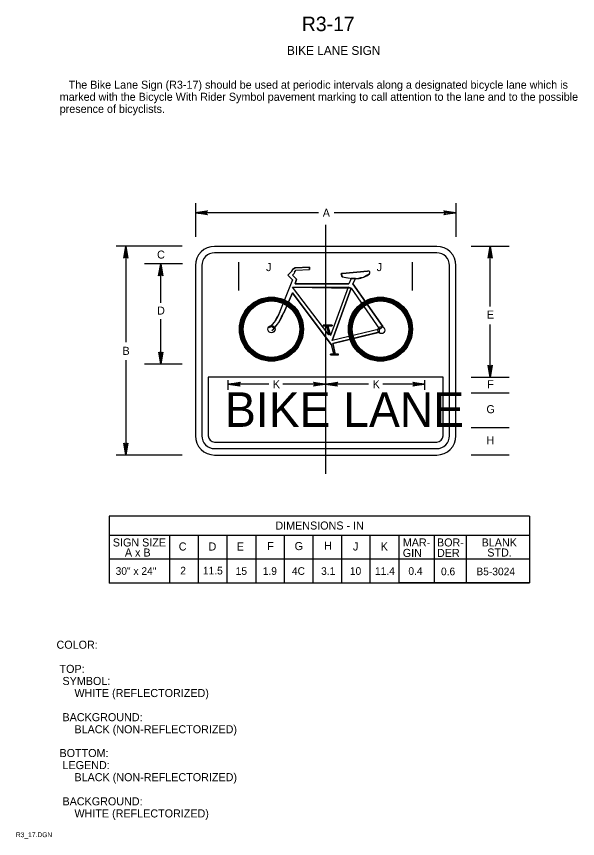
# Model space of a CAD drawing. Extents: x 0.013 to 0.187, y 0.004 to 0.259.
import ezdxf

# ---------------------------------------------------------------- set-up
doc = ezdxf.new("R2010")
doc.units = 0
for name, color, linetype in [('1', 7, 'Continuous'), ('2', 7, 'Continuous'), ('3', 7, 'Continuous')]:
    doc.layers.add(name, color=color, linetype=linetype)

# ---------------------------------------------------------------- blocks, each defined once
blk = doc.blocks.new('RARROW')
at = {"layer": '3'}
for p, q in [((-2.156, 0.28500000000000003), (-2.2665, 0.384625)), ((-2.2665, 0.384625), (0, 0)), ((0, 0), (-2.2665, -0.379125)), ((-2.156, 0.28500000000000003), (-2.075625, 0.12075)), ((0, 0), (-2.156, 0.28500000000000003)), ((-2.14975, -0.2705), (0, 0)), ((-2.075625, 0.12075), (0, 0)), ((0, 0), (-2.074, -0.108)), ((-2.2665, -0.379125), (-2.14975, -0.2705)), ((-2.074, -0.108), (-2.14975, -0.2705))]:
    blk.add_line(p, q, dxfattribs=at)

msp = doc.modelspace()

# ---------------------------------------------------------------- linework, layer by layer
at = {"layer": '1'}
msp.add_line((0.10875, 0.1945), (0.10875, 0.11721715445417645), dxfattribs=at)
at = {"layer": '3'}
for p, q in [((0.068275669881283, 0.20125), (0.068275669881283, 0.19081538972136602)), ((0.149275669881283, 0.20125), (0.149275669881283, 0.19081538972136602)), ((0.1065, 0.19825), (0.06825, 0.19825)), ((0.149275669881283, 0.19825), (0.1114455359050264, 0.19825)), ((0.06421562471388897, 0.18788002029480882), (0.04370848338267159, 0.18788002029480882)), ((0.046625, 0.18787500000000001), (0.046625, 0.158059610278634)), ((0.14327566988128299, 0.18781538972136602), (0.074275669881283, 0.18781538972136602)), ((0.16577656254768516, 0.18781538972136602), (0.15402656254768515, 0.18781538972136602)), ((0.15990156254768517, 0.169125), (0.15990156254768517, 0.18781538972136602)), ((0.14327566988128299, 0.18581538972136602), (0.074275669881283, 0.18581538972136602)), ((0.06424285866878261, 0.18236952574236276), (0.052492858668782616, 0.18236952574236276)), ((0.0575, 0.17025), (0.0575, 0.182375)), ((0.068275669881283, 0.18181538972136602), (0.068275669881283, 0.12901539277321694)), ((0.07027566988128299, 0.18181538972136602), (0.07027566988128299, 0.12901539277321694)), ((0.08175, 0.174125), (0.08175, 0.182875)), ((0.09925, 0.181125), (0.10375000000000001, 0.181375)), ((0.10375000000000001, 0.181375), (0.10375000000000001, 0.180625)), ((0.13575, 0.174125), (0.13575, 0.182875)), ((0.147275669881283, 0.12901539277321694), (0.147275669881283, 0.18181538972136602)), ((0.149275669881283, 0.12901539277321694), (0.149275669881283, 0.18181538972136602)), ((0.097, 0.178875), (0.09825, 0.180125)), ((0.0985, 0.177375), (0.097, 0.178875)), ((0.09825, 0.180125), (0.0985, 0.180625)), ((0.0985, 0.180625), (0.09875, 0.180875)), ((0.0985, 0.178875), (0.099, 0.179375)), ((0.09975, 0.177625), (0.0985, 0.178875)), ((0.09875, 0.180875), (0.09925, 0.181125)), ((0.099, 0.179375), (0.0995, 0.180375)), ((0.099, 0.179875), (0.0995, 0.180375)), ((0.0995, 0.180375), (0.10375000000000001, 0.180625)), ((0.114, 0.179375), (0.12175, 0.180125)), ((0.0985, 0.177375), (0.0945, 0.167625)), ((0.09975, 0.177625), (0.09925, 0.176125)), ((0.09925, 0.176125), (0.116, 0.176125)), ((0.11675, 0.177875), (0.116, 0.176125)), ((0.11800000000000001, 0.177875), (0.11725000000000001, 0.176125)), ((0.11725000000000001, 0.176125), (0.1265, 0.162875)), ((0.0985, 0.175125), (0.11575, 0.175125)), ((0.10975, 0.160375), (0.0985, 0.175125)), ((0.11575, 0.175125), (0.11025, 0.160125)), ((0.11675, 0.174875), (0.11075, 0.15862500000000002)), ((0.11675, 0.174875), (0.1255, 0.162125)), ((0.0985, 0.173375), (0.09575, 0.167125)), ((0.1105, 0.15737500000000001), (0.0985, 0.173375)), ((0.0575, 0.15125), (0.0575, 0.16522262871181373)), ((0.108, 0.163375), (0.109, 0.163375)), ((0.108, 0.163375), (0.108, 0.163125)), ((0.109, 0.163375), (0.11075, 0.163375)), ((0.11075, 0.163375), (0.11075, 0.163125)), ((0.15987500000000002, 0.147125), (0.15987500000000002, 0.16359756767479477)), ((0.108, 0.163125), (0.109, 0.163125)), ((0.109, 0.163125), (0.10975, 0.160375)), ((0.1095, 0.163125), (0.11075, 0.163125)), ((0.1095, 0.163125), (0.11025, 0.160125)), ((0.1255, 0.162125), (0.11075, 0.15862500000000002)), ((0.12525, 0.161125), (0.111, 0.15762500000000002)), ((0.1105, 0.15737500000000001), (0.11125, 0.154375)), ((0.111, 0.15762500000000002), (0.11175, 0.154375)), ((0.11025, 0.154375), (0.11125, 0.154375)), ((0.11025, 0.154125), (0.11025, 0.154375)), ((0.11025, 0.154125), (0.11125, 0.154125)), ((0.11125, 0.154125), (0.11275, 0.154125)), ((0.11175, 0.154375), (0.11275, 0.154375)), ((0.11275, 0.154125), (0.11275, 0.154375)), ((0.046625, 0.15249373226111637), (0.046625, 0.123)), ((0.06421562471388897, 0.15126539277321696), (0.05246562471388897, 0.15126539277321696)), ((0.07227566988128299, 0.14721538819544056), (0.07227566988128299, 0.12901539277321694)), ((0.145275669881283, 0.14721538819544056), (0.07227566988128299, 0.14721538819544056)), ((0.07227566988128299, 0.14721538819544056), (0.07227566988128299, 0.12901539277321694)), ((0.0785, 0.14325000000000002), (0.0785, 0.14621538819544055)), ((0.139625, 0.14325000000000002), (0.139625, 0.14621538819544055)), ((0.145275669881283, 0.12901539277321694), (0.145275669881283, 0.14721538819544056)), ((0.145275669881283, 0.12901539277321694), (0.145275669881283, 0.14721538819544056)), ((0.16577656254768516, 0.14713768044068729), (0.15402656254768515, 0.14713768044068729)), ((0.091125, 0.145), (0.0785, 0.145)), ((0.10875, 0.145), (0.0955, 0.145)), ((0.122125, 0.145), (0.10875, 0.145)), ((0.139625, 0.145), (0.1265, 0.145)), ((0.16577656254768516, 0.14221538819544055), (0.15402656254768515, 0.14221538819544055)), ((0.16577656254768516, 0.13141539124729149), (0.15402656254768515, 0.13141539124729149)), ((0.074275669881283, 0.12701539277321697), (0.14327566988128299, 0.12701539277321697)), ((0.074275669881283, 0.12701539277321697), (0.14327566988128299, 0.12701539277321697)), ((0.05246562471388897, 0.12301539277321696), (0.04370848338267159, 0.12301539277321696)), ((0.06421562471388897, 0.12301539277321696), (0.05246562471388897, 0.12301539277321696)), ((0.074275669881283, 0.12501539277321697), (0.14327566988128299, 0.12501539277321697)), ((0.074275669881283, 0.12301539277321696), (0.14327566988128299, 0.12301539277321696)), ((0.16577656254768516, 0.12301539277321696), (0.15402656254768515, 0.12301539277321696)), ((0.1720856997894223, 0.10401368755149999), (0.041481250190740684, 0.10401368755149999)), ((0.041522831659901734, 0.104025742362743), (0.041522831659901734, 0.083275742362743)), ((0.1720856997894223, 0.104025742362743), (0.1720856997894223, 0.08332574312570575)), ((0.1720856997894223, 0.09801368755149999), (0.041481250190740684, 0.09801368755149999)), ((0.060272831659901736, 0.098025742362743), (0.060272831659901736, 0.083275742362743)), ((0.06914783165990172, 0.098025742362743), (0.06914783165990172, 0.083275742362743)), ((0.07802283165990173, 0.098025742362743), (0.07802283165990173, 0.083275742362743)), ((0.08702283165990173, 0.098025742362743), (0.08702283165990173, 0.083275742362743)), ((0.09589783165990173, 0.098025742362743), (0.09589783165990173, 0.083275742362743)), ((0.10477283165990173, 0.098025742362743), (0.10477283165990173, 0.083275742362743)), ((0.11364783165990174, 0.098025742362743), (0.11364783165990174, 0.083275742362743)), ((0.12252283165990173, 0.098025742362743), (0.12252283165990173, 0.083275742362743)), ((0.13152283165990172, 0.098025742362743), (0.13152283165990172, 0.08332574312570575)), ((0.1720856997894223, 0.098025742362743), (0.13152283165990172, 0.098025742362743)), ((0.1424658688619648, 0.098025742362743), (0.1424658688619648, 0.08332574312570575)), ((0.15246069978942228, 0.098025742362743), (0.15246069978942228, 0.08332574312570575)), ((0.1720856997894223, 0.09063868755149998), (0.041481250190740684, 0.09063868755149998)), ((0.1720856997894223, 0.09067574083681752), (0.13152283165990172, 0.09067574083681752)), ((0.1720856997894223, 0.08326368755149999), (0.041481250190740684, 0.08326368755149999)), ((0.1720856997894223, 0.08332574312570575), (0.13152283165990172, 0.08332574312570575))]:
    msp.add_line(p, q, dxfattribs=at)
for points in [[(0.1265, 0.162875), (0.11725000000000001, 0.176125), (0.11800000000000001, 0.177875), (0.11675, 0.177875), (0.116, 0.176125), (0.09925, 0.176125), (0.09975, 0.177625), (0.0985, 0.178875), (0.099, 0.179375), (0.0995, 0.180375), (0.10375000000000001, 0.180625), (0.10375000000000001, 0.181375), (0.09925, 0.181125), (0.09875, 0.180875), (0.0985, 0.180625), (0.09825, 0.180125), (0.097, 0.178875), (0.0985, 0.177375), (0.0945, 0.167625), (0.094, 0.166375), (0.0935, 0.165625), (0.09275, 0.164125), (0.09175, 0.163125), (0.09275, 0.162375), (0.09325, 0.163125), (0.09425, 0.164125), (0.095, 0.165875), (0.09575, 0.167125), (0.0985, 0.173375), (0.1105, 0.15737500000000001), (0.11125, 0.154375), (0.11025, 0.154375), (0.11025, 0.154125), (0.11275, 0.154125), (0.11275, 0.154375), (0.11175, 0.154375), (0.111, 0.15762500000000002), (0.1255, 0.161125), (0.1255, 0.162125), (0.11075, 0.15862500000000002), (0.11675, 0.174875), (0.11575, 0.175125), (0.11025, 0.160125), (0.1095, 0.163125), (0.11075, 0.163125), (0.11075, 0.163375), (0.108, 0.163375), (0.108, 0.163125), (0.109, 0.163125), (0.10975, 0.160375), (0.0985, 0.175125), (0.11675, 0.174875), (0.1255, 0.162125)], [(0.12175, 0.180125), (0.114, 0.179375), (0.114, 0.179375), (0.11375, 0.179375), (0.1135, 0.179125), (0.11375, 0.178625), (0.114, 0.178375), (0.115, 0.178125), (0.117, 0.177875), (0.11875000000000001, 0.177875), (0.11975000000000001, 0.178125), (0.12025, 0.178125), (0.12075, 0.178375), (0.1215, 0.178875), (0.12225, 0.179125), (0.12225, 0.179375), (0.1225, 0.179375), (0.1225, 0.179875), (0.12225, 0.180125), (0.122, 0.180125)]]:
    msp.add_lwpolyline(points, close=True, dxfattribs=at)
for centre, radius in [((0.0919325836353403, 0.1620959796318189), 0.009945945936), ((0.0919325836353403, 0.1620959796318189), 0.009830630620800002), ((0.0919325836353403, 0.1620959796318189), 0.0097153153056), ((0.0919325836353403, 0.1620959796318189), 0.0095999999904), ((0.0919325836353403, 0.1620959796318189), 0.0094846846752), ((0.0919325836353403, 0.1620959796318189), 0.009369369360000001), ((0.0919325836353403, 0.1620959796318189), 0.0092540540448), ((0.0919325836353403, 0.1620959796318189), 0.0091387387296), ((0.0919325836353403, 0.1620959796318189), 0.0090234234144), ((0.1258064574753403, 0.1620959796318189), 0.009945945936), ((0.1258064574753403, 0.1620959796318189), 0.009830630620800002), ((0.1258064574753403, 0.1620959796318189), 0.0097153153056), ((0.1258064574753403, 0.1620959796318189), 0.0095999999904), ((0.1258064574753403, 0.1620959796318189), 0.0094846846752), ((0.1258064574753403, 0.1620959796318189), 0.009369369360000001), ((0.1258064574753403, 0.1620959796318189), 0.0092540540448), ((0.1258064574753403, 0.1620959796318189), 0.0091387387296), ((0.1258064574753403, 0.1620959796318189), 0.0090234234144), ((0.0919325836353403, 0.1620959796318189), 0.0089081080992), ((0.0919325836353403, 0.1620959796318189), 0.008792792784), ((0.1258064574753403, 0.1620959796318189), 0.0089081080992), ((0.1258064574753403, 0.1620959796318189), 0.008792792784), ((0.0919325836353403, 0.1620959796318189), 0.0010977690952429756), ((0.1260947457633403, 0.1618076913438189), 0.0010977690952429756)]:
    msp.add_circle(centre, radius, dxfattribs=at)
for centre, radius, start, end in [((0.07427566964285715, 0.1818153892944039), 0.006, 90, 180), ((0.14327566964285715, 0.1818153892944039), 0.006, 0, 90), ((0.07427566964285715, 0.1818153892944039), 0.004, 90, 180), ((0.14327566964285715, 0.1818153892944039), 0.004, 0, 90), ((0.11405870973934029, 0.17888877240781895), 0.000509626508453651, 81.86989722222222, 261.8698972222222), ((0.11822578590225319, 0.18432693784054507), 0.006539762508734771, 274.53958888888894, 309.0632305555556), ((0.1184551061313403, 0.1953392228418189), 0.017533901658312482, 255.23545833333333, 270.9420861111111), ((0.08293326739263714, 0.17160311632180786), 0.012352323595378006, 312.61111111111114, 340.70747500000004), ((0.08293326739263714, 0.17160311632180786), 0.013505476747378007, 312.61111111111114, 340.70747500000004), ((0.07427566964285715, 0.12901539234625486), 0.006, 180, 270), ((0.07427566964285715, 0.12901539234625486), 0.004, 180, 270), ((0.07427566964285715, 0.12901539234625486), 0.002, 180, 270), ((0.07427566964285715, 0.12901539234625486), 0.002, 180, 270), ((0.14327566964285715, 0.12901539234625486), 0.006, 270, 0), ((0.14327566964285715, 0.12901539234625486), 0.004, 270, 0), ((0.14327566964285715, 0.12901539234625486), 0.002, 270, 0), ((0.14327566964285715, 0.12901539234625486), 0.002, 270, 0)]:
    msp.add_arc(centre, radius, start, end, dxfattribs=at)

# ---------------------------------------------------------------- block references
at = {"layer": '3', "xscale": 0.0016545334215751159, "yscale": 0.0016366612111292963}
for p, rotation in [((0.06825, 0.19825), 180), ((0.046625, 0.18787500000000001), 90), ((0.15987500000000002, 0.18787500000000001), 90), ((0.0575, 0.182375), 90), ((0.0575, 0.15125), -90), ((0.15987500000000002, 0.147125), -90), ((0.0785, 0.145), 180), ((0.10875, 0.145), 180), ((0.046625, 0.123), -90)]:
    msp.add_blockref('RARROW', p, dxfattribs=dict(at, rotation=rotation))
for p in [(0.14925, 0.19825), (0.10875, 0.145), (0.139625, 0.145)]:
    msp.add_blockref('RARROW', p, dxfattribs=at)

# ---------------------------------------------------------------- texts
at = {"layer": '1'}
for s, height, p in [('R3-17', 0.0045000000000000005, (0.101375, 0.254625)), ('BIKE LANE SIGN', 0.00275025, (0.09675, 0.24725)), ('COLOR:', 0.0024997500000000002, (0.025125, 0.062875)), (' TOP:', 0.0024997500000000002, (0.025125, 0.055375)), ('  SYMBOL:', 0.0024997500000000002, (0.025125, 0.051625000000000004)), ('      WHITE (REFLECTORIZED)', 0.0024997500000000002, (0.025125, 0.047875)), ('  BACKGROUND:', 0.0024997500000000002, (0.025125, 0.040375)), ('      BLACK (NON-REFLECTORIZED)', 0.0024997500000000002, (0.025125, 0.036625)), (' BOTTOM:', 0.0024997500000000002, (0.025125, 0.02925)), ('  LEGEND:', 0.0024997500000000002, (0.025125, 0.025500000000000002)), ('      BLACK (NON-REFLECTORIZED)', 0.0024997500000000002, (0.025125, 0.021750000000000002)), ('  BACKGROUND:', 0.0024997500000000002, (0.025125, 0.01425)), ('      WHITE (REFLECTORIZED)', 0.0024997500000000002, (0.025125, 0.0105)), ('R3_17.DGN', 0.0015, (0.0125, 0.004375))]:
    msp.add_text(s, height=height, dxfattribs=at).set_placement(p)
at = {"layer": '2'}
for s, p in [('   The Bike Lane Sign (R3-17) should be used at periodic intervals along a designated bicycle lane which is', (0.026125, 0.23675000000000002)), ('marked with the Bicycle With Rider Symbol pavement marking to call attention to the lane and to the possible', (0.026125, 0.233)), ('presence of bicyclists.', (0.026125, 0.22925))]:
    msp.add_text(s, height=0.0024997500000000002, dxfattribs=at).set_placement(p)
at = {"layer": '3'}
for s, height, p in [('A', 0.0024997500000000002, (0.107875, 0.197)), ('C', 0.0024997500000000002, (0.056375, 0.184)), ('J', 0.0024997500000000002, (0.09025, 0.180125)), ('J', 0.0024997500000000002, (0.124625, 0.180125)), ('D', 0.0024997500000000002, (0.056375, 0.166625)), ('E', 0.0024997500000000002, (0.15887500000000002, 0.165375)), ('B', 0.0024997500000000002, (0.045625, 0.154125)), ('K', 0.0024997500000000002, (0.092375, 0.14375000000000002)), ('K', 0.0024997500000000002, (0.123375, 0.14375000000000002)), ('F', 0.0024997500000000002, (0.159, 0.14375000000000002)), ('BIKE LANE', 0.01074975, (0.0775, 0.13175)), ('G', 0.0024997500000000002, (0.15875, 0.136)), ('H', 0.0024997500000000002, (0.15875, 0.12637500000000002)), ('DIMENSIONS - IN', 0.0024997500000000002, (0.09314658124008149, 0.099875)), ('SIGN SIZE', 0.0024997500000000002, (0.042625, 0.094625)), ('MAR-', 0.0024997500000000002, (0.13275, 0.094625)), ('BOR-', 0.0024997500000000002, (0.143375, 0.094625)), ('BLANK', 0.0024997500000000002, (0.15725, 0.094625)), ('C', 0.0024997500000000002, (0.063125, 0.093375)), ('D', 0.0024997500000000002, (0.072375, 0.093375)), ('E', 0.0024997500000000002, (0.081125, 0.093375)), ('F', 0.0024997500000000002, (0.090625, 0.0935)), ('G', 0.0024997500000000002, (0.099125, 0.0935)), ('H', 0.0024997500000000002, (0.10825, 0.093625)), ('J', 0.0024997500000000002, (0.11725000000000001, 0.093375)), ('K', 0.0024997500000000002, (0.12587500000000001, 0.093375)), ('A x B', 0.0024997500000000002, (0.046375, 0.0915)), ('GIN', 0.0024997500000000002, (0.13275, 0.091375)), ('DER', 0.0024997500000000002, (0.143375, 0.091375)), ('STD.', 0.0024997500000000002, (0.159, 0.0915)), ('30" x 24"', 0.0023752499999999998, (0.043495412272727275, 0.08581237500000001)), ('2', 0.0023752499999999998, (0.06357353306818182, 0.08593737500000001)), ('11.5', 0.0023752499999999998, (0.07061755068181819, 0.08593737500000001)), ('15', 0.0023752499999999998, (0.08080517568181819, 0.08581237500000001)), ('1.9', 0.0023752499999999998, (0.08921304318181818, 0.08581237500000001)), ('4C', 0.0023752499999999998, (0.09828957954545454, 0.08581237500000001)), ('3.1', 0.0023752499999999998, (0.10736539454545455, 0.08581237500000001)), ('10', 0.0023752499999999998, (0.11629725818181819, 0.08581237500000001)), ('11.4', 0.0023752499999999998, (0.12410315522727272, 0.08581237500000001)), ('0.4', 0.0023752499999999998, (0.13448199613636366, 0.08581237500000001)), ('0.6', 0.0023752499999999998, (0.14461851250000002, 0.08568737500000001)), ('B5-3024', 0.0023752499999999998, (0.155618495, 0.08568737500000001))]:
    msp.add_text(s, height=height, dxfattribs=at).set_placement(p)

doc.saveas('drawing.dxf')
